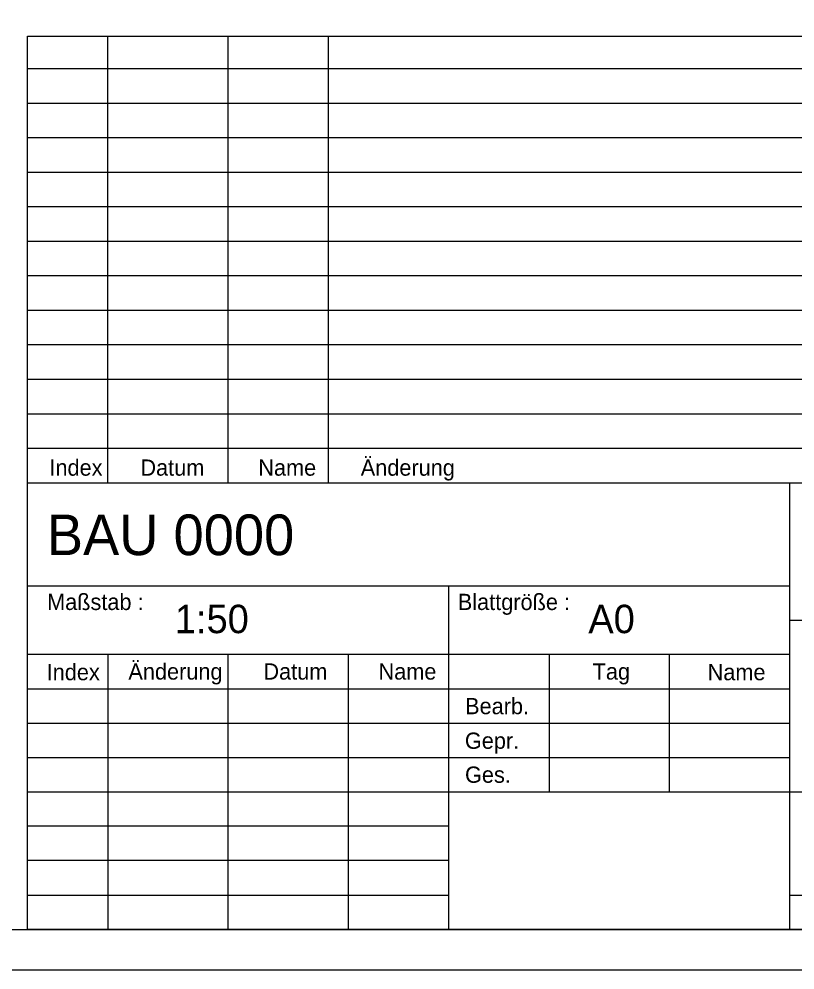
# Model space of a CAD drawing. Extents: x 0 to 59.5, y 0 to 42.1.
# Drawn here: x 50.25 to 55.03, y 0 to 5.85 of the extents above; entities that cross this region are included whole.
import ezdxf

# ---------------------------------------------------------------- set-up
doc = ezdxf.new("R2010")
doc.units = 0
doc.layers.add('90_Plankopf', color=7, linetype='Continuous')

msp = doc.modelspace()

# ---------------------------------------------------------------- linework, layer by layer
at = {"layer": '90_Plankopf'}
for p, q in [((50.306, 2.9995), (50.306, 5.749)), ((50.306, 5.749), (59.2, 5.749)), ((50.8001, 2.9995), (50.8001, 5.749)), ((51.5413, 2.9995), (51.5413, 5.749)), ((52.159, 2.9995), (52.159, 5.749)), ((50.306, 5.5495), (59.2, 5.5495)), ((50.306, 5.337), (59.2, 5.337)), ((50.306, 5.1245), (59.2, 5.1245)), ((50.306, 4.912), (59.2, 4.912)), ((50.306, 4.6995), (59.2, 4.6995)), ((50.306, 4.487), (59.2, 4.487)), ((50.306, 4.2745), (59.2, 4.2745)), ((50.306, 4.062), (59.2, 4.062)), ((50.306, 3.8495), (59.2, 3.8495)), ((50.306, 3.637), (59.2, 3.637)), ((50.306, 3.4245), (59.2, 3.4245)), ((50.306, 3.212), (59.2, 3.212)), ((50.306, 2.9995), (59.2, 2.9995)), ((50.306, 0.25), (50.306, 2.9995)), ((50.306, 2.9995), (59.2, 2.9995)), ((55.0001, 0.25), (55.0001, 2.9995)), ((50.306, 2.365), (55.0001, 2.365)), ((52.9001, 0.25), (52.9001, 2.365)), ((55.0001, 2.1535), (59.2, 2.1535)), ((50.306, 1.9435), (55.0001, 1.9435)), ((50.8001, 1.942), (50.8001, 0.25)), ((51.5413, 0.25), (51.5413, 1.942)), ((52.2825, 0.25), (52.2825, 1.942)), ((53.5177, 1.942), (53.5177, 1.096)), ((54.2589, 1.096), (54.2589, 1.942)), ((50.306, 1.7315), (55.0001, 1.7315)), ((50.306, 1.519), (55.0001, 1.519)), ((50.306, 1.3075), (55.0001, 1.3075)), ((50.306, 1.096), (55.0001, 1.096)), ((50.306, 1.096), (55.0001, 1.096)), ((52.9001, 1.096), (55.0001, 1.096)), ((55.0001, 1.096), (59.2, 1.096)), ((52.9001, 0.8845), (50.306, 0.8845)), ((52.9001, 0.673), (50.306, 0.673)), ((50.306, 0.4615), (52.9001, 0.4615)), ((55.0001, 0.4615), (59.2, 0.4615)), ((59.2, 0.25), (50.306, 0.25)), ((50.306, 0.25), (52.9001, 0.25)), ((50.89, 0.25), (59.2, 0.25)), ((50.89, 0.25), (59.2, 0.25))]:
    msp.add_line(p, q, dxfattribs=at)
for points in [[(0, 0), (59.45, 0), (59.45, 42.05), (0, 42.05)], [(1.25, 0.25), (59.2, 0.25), (59.2, 41.8), (1.25, 41.8)]]:
    msp.add_lwpolyline(points, close=True, dxfattribs=at)

# ---------------------------------------------------------------- texts
for s, height, p in [('Änderung', 0.1, (52.3579, 3.0428)), ('Index', 0.1, (50.4402, 3.0428)), ('Datum', 0.1, (51.0007, 3.0428)), ('Name', 0.1, (51.7269, 3.0428)), ('BAU 0000      ', 0.25, (50.4245, 2.5538)), ('Maßstab :', 0.1, (50.4258, 2.2158)), ('Blattgröße :', 0.099995, (52.9558, 2.2158)), ('1:50     ', 0.175, (51.2131, 2.0734)), ('A0       ', 0.175, (53.76, 2.0734)), ('Index', 0.1, (50.4235, 1.7837)), ('Änderung', 0.1, (50.9267, 1.7875)), ('Datum', 0.1, (51.7584, 1.7875)), ('Name', 0.1, (52.4674, 1.7875)), ('Tag', 0.1, (53.7862, 1.7875)), ('Name', 0.1, (54.4946, 1.7837)), ('Bearb.', 0.1, (53.0007, 1.5745)), ('Gepr.', 0.1, (52.9995, 1.3615)), ('Ges.', 0.1, (53.0002, 1.1523))]:
    msp.add_text(s, height=height, dxfattribs=at).set_placement(p)

doc.saveas('drawing.dxf')
